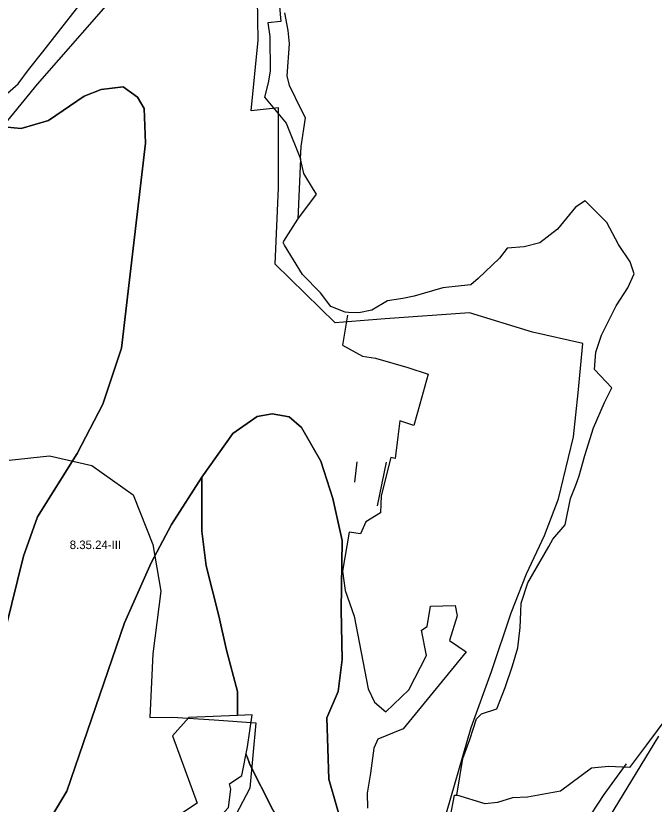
# Model space of a CAD drawing. Extents: x -547623 to -533936, y -1096714 to -1086523.
# Drawn here: x -541585 to -540837, y -1092131 to -1091207 of the extents above; entities that cross this region are included whole.
import ezdxf

# ---------------------------------------------------------------- set-up
doc = ezdxf.new("R2010")
doc.units = 0
for name, color, linetype in [('Vrstva 27', 7, 'Continuous'), ('Vrstva 28', 7, 'Continuous'), ('Vrstva 29', 7, 'Continuous')]:
    doc.layers.add(name, color=color, linetype=linetype)

msp = doc.modelspace()

# ---------------------------------------------------------------- linework, layer by layer
at = {"layer": 'Vrstva 28'}
for p, q in [((-541505, -1091301.5), (-541485, -1091293.5)), ((-541485, -1091293.5), (-541459, -1091290.5)), ((-541459, -1091290.5), (-541442.5, -1091302.5)), ((-541546.5, -1091330), (-541505, -1091301.5)), ((-541442.5, -1091302.5), (-541434.5, -1091316)), ((-541434.5, -1091316), (-541433, -1091356.5)), ((-541578.5, -1091339.5), (-541546.5, -1091330)), ((-541603.5, -1091337), (-541578.5, -1091339.5)), ((-541433, -1091356.5), (-541461, -1091597)), ((-541461, -1091597), (-541483, -1091662.5)), ((-541483, -1091662.5), (-541513, -1091720.5)), ((-541513, -1091720.5), (-541559.5, -1091794.5)), ((-541187.5, -1091754), (-541185, -1091730)), ((-541151, -1091730.5), (-541161.5, -1091781.5)), ((-541402.5, -1091803.5), (-541367, -1091748)), ((-541367, -1091747.71), (-541367, -1091811.5)), ((-541559.5, -1091794.5), (-541576, -1091840.5)), ((-541426.5, -1091848.5), (-541402.5, -1091803.5)), ((-541367, -1091811.5), (-541362, -1091852)), ((-541576, -1091840.5), (-541596.5, -1091924.5)), ((-541457.5, -1091919), (-541426.5, -1091848.5)), ((-541362, -1091852), (-541347, -1091910.5)), ((-541347, -1091910.5), (-541338, -1091951)), ((-541525, -1092116), (-541457.5, -1091919)), ((-541338, -1091951), (-541325, -1091999.5)), ((-541325, -1091999.5), (-541325, -1092027.4)), ((-541313.83, -1092075.71), (-541310.5, -1092085)), ((-541310.5, -1092085), (-541284.5, -1092136.5)), ((-541557.5, -1092170), (-541525, -1092116))]:
    msp.add_line(p, q, dxfattribs=at)
for points in [[(-541279.09, -1091160.99), (-541274.44, -1091213.91), (-541289.69, -1091215.69), (-541287.12, -1091231.55), (-541286.92, -1091272.24), (-541289.37, -1091285.92), (-541293.56, -1091302.71), (-541268.3, -1091333.32), (-541251.45, -1091374.92), (-541250.43, -1091360.42), (-541245.54, -1091327), (-541250.67, -1091317.09), (-541264.11, -1091288.87), (-541266.95, -1091277.5), (-541264.25, -1091240.12), (-541265.83, -1091224.53), (-541269.62, -1091203.79)], [(-541598.01, -1091195.68), (-541632.32, -1091233.95), (-541625.35, -1091238.85), (-541656.01, -1091274.32), (-541628.2, -1091289.12), (-541610.51, -1091311.34), (-541582.05, -1091287.09), (-541569.93, -1091270.69), (-541553.43, -1091249.53), (-541539.32, -1091231.42), (-541506.84, -1091190.12)], [(-540820.89, -1092028.37), (-540845.97, -1092061.78), (-540865.8, -1092088.26), (-540890.46, -1092087.32), (-540910.28, -1092089.18), (-540946.51, -1092116.22), (-540985.19, -1092123.11), (-541002.91, -1092123.83), (-541020.6, -1092129.25), (-541034.84, -1092130.91), (-541068.1, -1092120.72), (-541061.05, -1092077.76), (-541052.91, -1092055.56), (-541045, -1092031.17), (-541039.1, -1092025.56), (-541021.33, -1092019.8), (-541011.3, -1091994.81), (-541002.72, -1091969.4), (-540996.44, -1091947.99), (-540993.7, -1091924.45), (-540993.04, -1091906.13), (-540992.77, -1091895.59), (-540984.82, -1091872.11), (-540960.42, -1091829.44), (-540955.39, -1091820.65), (-540941.12, -1091803.86), (-540935.05, -1091773.28), (-540928.62, -1091757.59), (-540924.53, -1091746.55), (-540918.2, -1091722.58), (-540908.06, -1091690.41), (-540895.06, -1091660.69), (-540886.4, -1091643.22), (-540906.58, -1091622.02), (-540905.13, -1091601.74), (-540898.5, -1091581.65), (-540893.72, -1091572.11), (-540892.57, -1091569.82), (-540881.31, -1091547.35), (-540867.61, -1091525.99), (-540860.09, -1091509.83), (-540865.06, -1091495.66), (-540878.79, -1091475.2), (-540892.32, -1091449.46), (-540917.62, -1091424.08), (-540928.84, -1091431.67), (-540949.99, -1091457.53), (-540970.76, -1091473.31), (-540989.25, -1091478.28), (-541008.94, -1091479.86), (-541018.06, -1091491.46), (-541043.18, -1091515.21), (-541051.84, -1091522.6), (-541062.86, -1091523.8), (-541084.42, -1091526.16), (-541118.07, -1091535.82), (-541131.21, -1091538.64), (-541149.21, -1091541.41), (-541167.9, -1091552.52), (-541182.85, -1091555.6), (-541195, -1091554.92), (-541199.08, -1091554.53), (-541215.73, -1091548.16), (-541228.01, -1091532.06), (-541248.82, -1091510.36), (-541269.88, -1091475.99), (-541271.75, -1091472.94), (-541270.76, -1091471.37), (-541254.5, -1091445.52), (-541232.64, -1091416.41), (-541236.08, -1091410.8), (-541247.39, -1091392.03), (-541251.45, -1091374.92), (-541250.43, -1091360.42), (-541245.54, -1091327), (-541250.67, -1091317.09), (-541264.11, -1091288.87), (-541266.95, -1091277.5), (-541264.25, -1091240.12), (-541265.83, -1091224.53), (-541269.62, -1091203.79)], [(-541596.5, -1091924.5), (-541576, -1091840.5), (-541559.5, -1091794.5), (-541513, -1091720.5), (-541483, -1091662.5), (-541461, -1091597), (-541433, -1091356.5), (-541434.5, -1091316), (-541442.5, -1091302.5), (-541459, -1091290.5), (-541485, -1091293.5), (-541505, -1091301.5), (-541546.5, -1091330), (-541578.5, -1091339.5), (-541603.5, -1091337)], [(-541596.5, -1091924.5), (-541576, -1091840.5), (-541559.5, -1091794.5), (-541513, -1091720.5), (-541483, -1091662.5), (-541461, -1091597), (-541433, -1091356.5), (-541434.5, -1091316), (-541442.5, -1091302.5), (-541459, -1091290.5), (-541485, -1091293.5), (-541505, -1091301.5), (-541546.5, -1091330), (-541578.5, -1091339.5), (-541603.5, -1091337)], [(-541247.39, -1091392.03), (-541251.45, -1091374.92), (-541254.5, -1091445.52), (-541232.64, -1091416.41), (-541236.08, -1091410.8), (-541247.39, -1091392.03)], [(-541196.12, -1091558.29), (-541202.22, -1091593.38), (-541178.5, -1091606.11), (-541163.3, -1091608.46), (-541125.62, -1091619.59), (-541101.58, -1091627.55), (-541111.49, -1091662.59), (-541118.6, -1091687.71), (-541134.7, -1091682.18), (-541137.42, -1091700.95), (-541140.38, -1091726.11), (-541145.25, -1091725.04), (-541156.84, -1091769.85), (-541157.13, -1091779.84), (-541157.43, -1091789.98), (-541174.76, -1091800.45), (-541180.88, -1091814.62), (-541194.09, -1091812.5), (-541202.1, -1091858.34), (-541199.05, -1091881.01), (-541188.31, -1091910.97), (-541172.19, -1091996.09), (-541164.68, -1092011.93), (-541151.4, -1092023.14), (-541124.42, -1091997.22), (-541103.47, -1091957.26), (-541109.46, -1091927.59), (-541102.69, -1091923.09), (-541098.83, -1091899.37), (-541070.14, -1091898.63), (-541067.8, -1091910.68), (-541076.77, -1091939.42), (-541057.33, -1091952.81), (-541131.11, -1092042.96), (-541160.56, -1092055.13), (-541165.29, -1092065.84), (-541169.3, -1092095.12), (-541173.08, -1092118.45), (-541172.63, -1092136.11)], [(-541191, -1092196), (-541218, -1092102), (-541220.5, -1092030), (-541207, -1091999.5), (-541202.5, -1091962), (-541203.5, -1091903.5), (-541202.5, -1091822.5), (-541213.5, -1091773), (-541227.5, -1091729.5), (-541250, -1091690), (-541264.5, -1091677.5), (-541284.5, -1091674), (-541302, -1091677), (-541330.5, -1091697), (-541367, -1091748), (-541402.5, -1091803.5), (-541426.5, -1091848.5), (-541457.5, -1091919), (-541525, -1092116), (-541557.5, -1092170)], [(-541325, -1092026.8), (-541325, -1091999.5), (-541338, -1091951), (-541347, -1091910.5), (-541362, -1091852), (-541367, -1091811.5), (-541367, -1091748), (-541330.5, -1091697), (-541302, -1091677), (-541284.5, -1091674), (-541264.5, -1091677.5), (-541250, -1091690), (-541227.5, -1091729.5), (-541213.5, -1091773), (-541202.5, -1091822.5), (-541203.5, -1091903.5), (-541202.5, -1091962), (-541207, -1091999.5), (-541220.5, -1092030), (-541218, -1092102), (-541191, -1092196)], [(-541325, -1092027.3), (-541382.13, -1092029.93), (-541401.47, -1092051.31), (-541372.32, -1092130.22), (-541392.03, -1092143.08), (-541390.03, -1092144.87), (-541368.66, -1092164.02), (-541349.05, -1092149.56), (-541335.58, -1092135.1), (-541332.83, -1092113.79), (-541334.35, -1092107.73), (-541320.2, -1092097.81), (-541313.25, -1092064.19), (-541308.14, -1092026.52), (-541325, -1092027.3)], [(-540990.6, -1092592.86), (-541012, -1092562.5), (-541095, -1092484.5), (-541142.5, -1092433), (-541199.5, -1092335.5), (-541247, -1092245.5), (-541250, -1092236.27), (-541280, -1092144), (-541284.5, -1092136.5), (-541310.5, -1092085), (-541314.97, -1092072.5)], [(-540816, -1092554), (-540843, -1092581), (-540857, -1092603.5), (-540866, -1092630.5), (-540868, -1092652.5), (-540897, -1092588), (-540941.5, -1092529.5), (-541002.5, -1092435), (-541032, -1092399), (-541078, -1092343.5), (-541116.5, -1092306.5), (-541071, -1092296.5), (-541039.5, -1092286), (-541012.5, -1092271), (-540995, -1092256.5), (-540941.5, -1092190.5), (-540895.5, -1092120), (-540873.5, -1092090), (-540869.14, -1092084.08)], [(-541159.34, -1092219.37), (-541156.04, -1092234.4), (-541142.1, -1092273.29), (-541137.67, -1092272.07), (-541143.56, -1092233.33), (-541126.48, -1092211.14), (-541097.86, -1092180.23), (-541093.75, -1092168.92), (-541075.81, -1092147.25), (-541070.87, -1092120.77), (-541068.1, -1092120.72)]]:
    msp.add_lwpolyline(points, dxfattribs=at)
at = {"layer": 'Vrstva 29'}
for points in [[(-541457.15, -1091169.68), (-541559.84, -1091287.31), (-541619.19, -1091359.72)], [(-541084.45, -1092156.29), (-541051.19, -1092041.6), (-541027.62, -1091975.79), (-541004.51, -1091907.11), (-540986.46, -1091861.45), (-540965.44, -1091816.62), (-540948.97, -1091773.6), (-540931.32, -1091701), (-540925.93, -1091649.34), (-540920.36, -1091591.3), (-540979.59, -1091578.19), (-541053.12, -1091555.33), (-541151.93, -1091562.49), (-541210.54, -1091567.11), (-541280.84, -1091498.25), (-541277.21, -1091408.76), (-541277.24, -1091315.28), (-541309.1, -1091318.72), (-541300.82, -1091235.89), (-541301.86, -1091186.86)], [(-541592.89, -1091728.28), (-541545.47, -1091722.95), (-541496.02, -1091734.22), (-541447.57, -1091768.7), (-541424.5, -1091827.04), (-541414.85, -1091881.61), (-541424.44, -1091955.35), (-541427.7, -1092029.77), (-541401.29, -1092029.32), (-541352.5, -1092032.58), (-541303.74, -1092036.1), (-541310.54, -1092112.45), (-541356.43, -1092199.89)], [(-540831.9, -1092051.66), (-540931.11, -1092214.74)]]:
    msp.add_lwpolyline(points, dxfattribs=at)

# ---------------------------------------------------------------- texts
at = {"layer": 'Vrstva 27'}
msp.add_text('8.35.24-III', height=10, dxfattribs=at).set_placement((-541521.76, -1091832.39))

doc.saveas('drawing.dxf')
